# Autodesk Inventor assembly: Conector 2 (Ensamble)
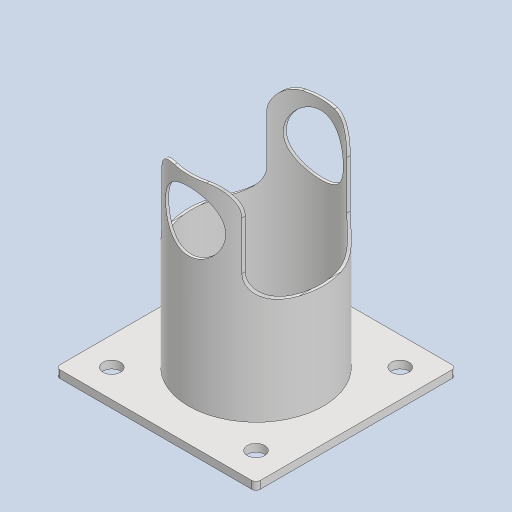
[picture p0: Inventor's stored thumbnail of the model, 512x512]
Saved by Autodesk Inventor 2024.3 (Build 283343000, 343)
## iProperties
Created: 2025-10
Part Number: Conector 2 (Ensamble)
Document SubType Name: Assembly
Designer: Asus
Author: Asus
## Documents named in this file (3)
- D:\2025\Anclajes Guadua\Conector Base (Ensamble).iam
- D:\2025\Anclajes Guadua\Base Platina.ipt
- D:\2025\Anclajes Guadua\Tuberia Conector 2.ipt
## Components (2 placed, 2 different names)
1. Base Platina:1 — Nivelación:1, Nivelación:2, Coincidencia:1, Coincidencia:2
2. Tuberia Conector 2:1 — Coincidencia:2, Nivelación:3, Nivelación:4
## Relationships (6: Flush 4, Mate 2)
- Nivelación:1 [Flush]: Base Platina:1
- Nivelación:2 [Flush]: Base Platina:1
- Coincidencia:1 [Mate]: Base Platina:1
- Coincidencia:2 [Mate]: Base Platina:1 ↔ Tuberia Conector 2:1
- Nivelación:3 [Flush]: Tuberia Conector 2:1
- Nivelación:4 [Flush]: Tuberia Conector 2:1
